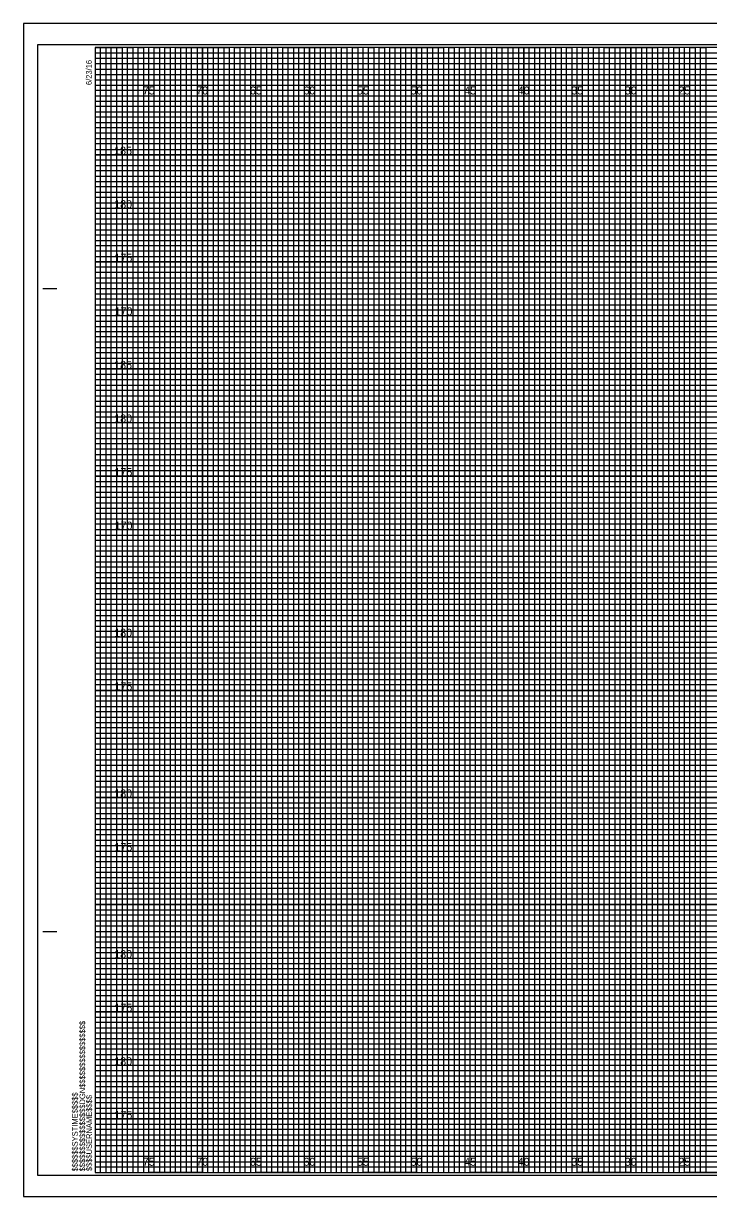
# Model space of a CAD drawing. Extents: x -7 to 162, y -2 to 767.
# Drawn here: x -6.7 to 57.2, y -2.2 to 107.2 of the extents above; entities that cross this region are included whole.
import ezdxf

# ---------------------------------------------------------------- set-up
doc = ezdxf.new("R2010")
doc.units = 0
for name, color, linetype in [('Exist Cross Section Cell', 7, 'Continuous'), ('Prop CMT Pvmt Course 1', 7, 'Continuous'), ('Prop CMT Pvmt Course 1 Wedge', 7, 'Continuous'), ('Prop CMT Pvmt Course 2', 7, 'Continuous'), ('Prop CMT Pvmt Course 3', 7, 'Continuous'), ('Prop CMT Pvmt Surface Shoulder', 7, 'Continuous'), ('Prop CMT Shld Paved Course 2', 7, 'Continuous'), ('Prop CMT Shld Paved Course 3', 7, 'Continuous'), ('Prop CMT Slope Grass', 7, 'Continuous'), ('Prop CMT Subgrade Earthwork', 7, 'Continuous'), ('Scratch_Level_0', 7, 'Continuous')]:
    doc.layers.add(name, color=color, linetype=linetype)

msp = doc.modelspace()

# ---------------------------------------------------------------- linework, layer by layer
at = {"layer": 'Prop CMT Pvmt Course 1'}
for p, q in [((0, 104.5), (130, 104.5)), ((130, 103.99), (0, 103.99)), ((0, 103.99), (0, 103.5)), ((0, 103.5), (130, 103.5)), ((130, 102.95), (0, 102.95)), ((0, 102.95), (0, 102)), ((0, 102), (160, 102))]:
    msp.add_line(p, q, dxfattribs=at)
for points in [[(0, 101.5), (135, 101.5), (160, 101.5), (160, 101), (0, 101)], [(0, 100.5), (160, 100.5), (160, 99.5), (0, 99.5)], [(0, 99), (160, 99), (160, 98.5), (0, 98.49)], [(0, 98), (160, 98), (160, 97), (0, 97)], [(0, 96.5), (160, 96.5), (160, 96), (0, 96)], [(0, 95.5), (160, 95.5), (160, 94.5), (0, 94.5)], [(0, 94), (160, 94), (160, 93.5), (0, 93.5)], [(0, 93), (160, 93), (160, 92), (0, 92)], [(0, 91.5), (160, 91.5), (160, 91), (0, 91)], [(0, 90.5), (160, 90.5), (160, 89.5), (0, 89.5)], [(0, 89), (160, 89), (160, 88.5), (0, 88.5)], [(0, 88), (160, 88), (160, 86.98), (160, 86.5), (160, 86), (0, 86)], [(0, 87), (160, 87), (160, 86.5), (0, 86.5)], [(0, 85.5), (160, 85.5), (160, 84.5), (0, 84.52)], [(0, 84.52), (160, 84.5), (160, 84), (0, 84)], [(0, 83.5), (160, 83.5), (160, 83), (0, 83)], [(0, 82), (160, 82), (160, 81.5), (0, 81.5)], [(0, 81), (160, 81), (160, 80.5), (0, 80.5)], [(-0.04, 79.45), (160, 79.45), (160, 78.94), (-0.04, 78.94)], [(0, 78.5), (160, 78.5), (160, 78), (0, 78)], [(0, 77), (160, 77), (160, 76.5), (0, 76.5)], [(0, 76), (160, 76), (160, 75.5), (0, 75.5)], [(0, 74.5), (160, 74.5), (160, 74), (0, 74)], [(0, 73.5), (160, 73.5), (160, 73), (0, 73)], [(0, 72), (160, 72), (160, 71.5), (0, 71.5)], [(0, 71), (160, 71), (160, 70.5), (0, 70.5)], [(0, 69.5), (160, 69.5), (160, 68.99), (0, 69)], [(0, 68.5), (160, 68.5), (160, 68), (0, 68)], [(0, 67), (160, 67), (160, 66.5), (0, 66.5)], [(0, 66), (160, 66), (160, 65.5), (0, 65.5)], [(0, 64.5), (160, 64.5), (160, 64), (0, 64)], [(0, 63.5), (160, 63.5), (160, 63), (0, 63)], [(0, 62), (160, 62), (160, 61.5), (0, 61.5)], [(0, 61), (160, 61), (160, 60.5), (0, 60.5)], [(0, 59.5), (160, 59.5), (160, 59), (0, 59)], [(0, 58.5), (160.03, 58.45), (160, 58), (0, 58)], [(0, 57), (160, 57), (160, 56.5), (0, 56.5)], [(0, 56), (160, 56), (160, 55.5), (0, 55.5)], [(0, 54.5), (160, 54.5), (160, 54), (0, 54)], [(0, 53.5), (160, 53.5), (160, 53), (0, 53)], [(0, 52), (160, 52), (160, 51.5), (0, 51.5)], [(0, 51), (160, 51), (160, 50.5), (0, 50.5)], [(0, 49.5), (160, 49.5), (160, 49), (0, 49)], [(0, 48.5), (160, 48.5), (160, 48), (0, 48)], [(0, 47), (160, 47), (160, 46.5), (0, 46.5)], [(0, 46), (160, 46), (160, 45.5), (0, 45.5)], [(0, 44.5), (160, 44.5), (160, 44), (0, 44)], [(0, 43.5), (160, 43.5), (160, 43), (0, 43)], [(0, 42), (160, 42), (160, 41.5), (0, 41.5)], [(0, 41), (160, 41), (160, 40.5), (0, 40.5)], [(0, 39.5), (160, 39.5), (160, 38.99), (0, 39)], [(0, 38.5), (160, 38.5), (160, 38), (0, 38)], [(0, 37), (160, 37), (160, 36.5), (0, 36.5)], [(0, 36), (160, 36), (160, 35.5), (0, 35.5)], [(0, 34.5), (160, 34.5), (160, 34), (0, 34)], [(0, 33.5), (160, 33.5), (160, 33), (0, 33)], [(0, 32), (160, 32), (160, 31.5), (0, 31.5)], [(0, 31), (160, 31), (160, 30.5), (0, 30.5)], [(0, 29.5), (160, 29.5), (160, 29), (0, 29)], [(0, 28.5), (160.03, 28.46), (160, 28), (0, 28)], [(0, 27), (160, 27), (160, 26.5), (0, 26.5)], [(0, 26), (160, 26), (160, 25.5), (0, 25.5)], [(0, 24.5), (160, 24.5), (160, 24), (0, 24)], [(0, 23.5), (160, 23.5), (160, 23), (0, 23)], [(0, 22), (160, 22), (160, 21.5), (0, 21.5)], [(0, 21), (160, 21), (160, 20.5), (0, 20.5)], [(0, 19.5), (160, 19.5), (160, 19), (0, 19)], [(0, 18.5), (160, 18.5), (160, 18), (0, 18)], [(0, 17), (160, 17), (160, 16.5), (0, 16.5)], [(0, 16), (160, 16), (160, 15.5), (0, 15.5)], [(0, 14.5), (160, 14.5), (160, 14), (0, 14)], [(0, 13.5), (160, 13.5), (160, 13), (0, 13)], [(0, 12), (160, 12), (160, 11.5), (0, 11.5)], [(0, 11), (160, 11), (160, 10.5), (0, 10.5)], [(0, 9.5), (160, 9.5), (160, 9), (0, 9)], [(0, 8.5), (160, 8.5), (160, 8), (0, 8)], [(0, 7), (160, 7), (160, 6.5), (0, 6.5)], [(0, 6), (160, 6), (160, 5.5), (0, 5.5)], [(0, 4.5), (160, 4.5), (160, 4), (0, 4)], [(0, 3.5), (160, 3.5), (160, 3), (0, 3)], [(0, 2), (160, 2), (160, 1.5), (0, 1.5)], [(0, 1), (160, 1), (160, 0.5), (0, 0.5)]]:
    msp.add_lwpolyline(points, dxfattribs=at)
at = {"layer": 'Prop CMT Pvmt Course 2'}
for p, q in [((5, 0), (5, 105)), ((10, 0), (10, 105)), ((15, 0), (15, 105)), ((20, 0), (20, 105)), ((25, 0), (25, 105)), ((30, 0), (30, 105)), ((35, 0), (35, 105)), ((40, 0), (40, 105)), ((45, 0), (45, 105)), ((50, 0), (50, 105)), ((55, 0), (55, 105)), ((0, 100), (160, 100)), ((0, 95), (160, 95)), ((0, 90), (160, 90)), ((0, 85), (160, 85)), ((0, 80), (160, 80)), ((0, 75), (160, 75)), ((0, 70), (160, 70)), ((0, 65), (160, 65)), ((0, 60), (160, 60)), ((0, 55), (160, 55)), ((0, 50), (160, 50)), ((0, 45), (160, 45)), ((0, 40), (160, 40)), ((0, 35), (160, 35)), ((0, 30), (160, 30)), ((0, 25), (160, 25)), ((0, 20), (160, 20)), ((0, 15), (160, 15)), ((0, 10), (160, 10)), ((0, 5), (160, 5))]:
    msp.add_line(p, q, dxfattribs=at)
at = {"layer": 'Prop CMT Pvmt Course 3'}
for p, q in [((161.65, 107.25), (-6.7, 107.25)), ((-6.7, 107.25), (-6.7, -2.25)), ((-6.7, -2.25), (161.65, -2.25))]:
    msp.add_line(p, q, dxfattribs=at)
at = {"layer": 'Prop CMT Pvmt Surface Shoulder'}
for points in [[(0, 105), (2.5, 105), (2.5, 0), (7.5, 0), (7.5, 105), (12.5, 105), (12.5, 0), (17.5, 0), (17.5, 105), (22.5, 105), (22.5, 0), (27.5, 0), (27.5, 105), (32.5, 105), (32.5, 0), (37.5, 0), (37.5, 105), (42.5, 105), (42.5, 0), (47.5, 0), (47.5, 105), (52.5, 105), (52.5, 0), (57.5, 0)], [(0, 102.5), (137.5, 102.5)], [(0, 92.5), (160, 92.5), (160, 97.5), (0, 97.5)], [(0, 82.5), (160, 82.5), (160, 87.5), (0, 87.5)], [(0, 72.5), (160, 72.5), (160, 77.5), (0, 77.5)], [(0, 62.5), (160, 62.5), (160, 67.5), (0, 67.5)], [(0, 52.5), (160, 52.5), (160, 57.5), (0, 57.5)], [(0, 42.5), (160, 42.5), (160, 47.5), (0, 47.5)], [(0, 32.5), (160, 32.5), (160, 37.5), (0, 37.5)], [(0, 22.5), (160, 22.5), (160, 27.5), (0, 27.5)], [(0, 12.5), (160, 12.5), (160, 17.5), (0, 17.5)], [(0, 2.5), (160, 2.5), (160, 7.5), (0, 7.5)]]:
    msp.add_lwpolyline(points, dxfattribs=at)
at = {"layer": 'Prop CMT Shld Paved Course 2'}
msp.add_lwpolyline([(-6.7, -2.25), (161.65, -2.25), (161.65, 107.25), (-6.7, 107.25)], close=True, dxfattribs=at)
at = {"layer": 'Prop CMT Shld Paved Course 3'}
msp.add_lwpolyline([(-5.4, -0.25), (161.2, -0.25), (161.2, 105.25), (-5.4, 105.25)], close=True, dxfattribs=at)
at = {"layer": 'Prop CMT Slope Grass'}
for points in [[(0, 0), (0.5, 0), (0.5, 105), (1, 105), (1, 0)], [(1, 0), (1.5, 0), (1.5, 105), (2, 105), (2, 0)], [(2.5, 0), (3, 0), (3, 105), (3.5, 105), (3.5, 0)], [(3.5, 0), (4, 0), (4, 105), (4.5, 105), (4.5, 0)], [(5, 0), (5.5, 0), (5.5, 105), (6, 105), (6, 0)], [(6, 0), (6.5, 0), (6.5, 105), (7, 105), (7, 0)], [(7.5, 0), (8, 0), (8, 105), (8.5, 105), (8.5, 0)], [(8.5, 0), (9, 0), (9, 105), (9.5, 105), (9.5, 0)], [(10, 0), (10.5, 0), (10.5, 105), (11, 105), (11, 0)], [(11, 0), (11.5, 0), (11.5, 105), (12, 105), (12, 0)], [(12.5, 0), (13, 0), (13, 105), (13.5, 105), (13.5, 0)], [(13.5, 0), (14, 0), (14, 105), (14.5, 105), (14.5, 0)], [(15, 0), (15.5, 0), (15.5, 105), (16, 105), (16, 0)], [(16, 0), (16.5, 0), (16.5, 105), (17, 105), (17, 0)], [(17.5, 0), (18, 0), (18, 105), (18.5, 105), (18.5, 0)], [(18.5, 0), (19, 0), (19, 105), (19.5, 105), (19.5, 0)], [(20, 0), (20.5, 0), (20.5, 105), (21, 105), (21, 0)], [(21, 0), (21.5, 0), (21.5, 105), (22, 105), (22, 0)], [(22.5, 0), (23, 0), (23, 105), (23.5, 105), (23.5, 0)], [(23.5, 0), (24, 0), (24, 105), (24.5, 105), (24.5, 0)], [(25, 0), (25.5, 0), (25.5, 105), (26, 105), (26, 0)], [(26, 0), (26.5, 0), (26.5, 105), (27, 105), (27, 0)], [(27.5, 0), (28, 0), (28, 105), (28.5, 105), (28.5, 0)], [(28.5, 0), (29, 0), (29, 105), (29.5, 105), (29.5, 0)], [(30, 0), (30.5, 0), (30.5, 105), (31, 105), (31, 0)], [(31, 0), (31.5, 0), (31.5, 105), (32, 105), (32, 0)], [(32.5, 0), (33, 0), (33, 105), (33.5, 105), (33.5, 0)], [(33.5, 0), (34, 0), (34, 105), (34.5, 105), (34.5, 0)], [(35, 0), (35.5, 0), (35.5, 105), (36, 105), (36, 0)], [(36, 0), (36.5, 0), (36.5, 105), (37, 105), (37, 0)], [(37.5, 0), (38, 0), (38, 105), (38.5, 105), (38.5, 0)], [(38.5, 0), (39, 0), (39, 105), (39.5, 105), (39.5, 0)], [(40, 0), (40.5, 0), (40.5, 105), (41, 105), (41, 0)], [(41, 0), (41.5, 0), (41.5, 105), (42, 105), (42, 0)], [(42.5, 0), (43, 0), (43, 105), (43.5, 105), (43.5, 0)], [(43.5, 0), (44, 0), (44, 105), (44.5, 105), (44.5, 0)], [(45, 0), (45.5, 0), (45.5, 105), (46, 105), (46, 0)], [(46, 0), (46.5, 0), (46.5, 105), (47, 105), (47, 0)], [(47.5, 0), (48, 0), (48, 105), (48.5, 105), (48.5, 0)], [(48.5, 0), (49, 0), (49, 105), (49.5, 105), (49.5, 0)], [(50, 0), (50.5, 0), (50.5, 105), (51, 105), (51, 0)], [(51, 0), (51.5, 0), (51.5, 105), (52, 105), (52, 0)], [(52.5, 0), (53, 0), (53, 105), (53.5, 105), (53.5, 0)], [(53.5, 0), (54, 0), (54, 105), (54.5, 105), (54.5, 0)], [(55, 0), (55.5, 0), (55.5, 105), (56, 105), (56, 0)], [(56, 0), (56.5, 0), (56.5, 105), (57, 105), (57, 0)]]:
    msp.add_lwpolyline(points, dxfattribs=at)
at = {"layer": 'Prop CMT Subgrade Earthwork'}
for p, q in [((-4.9, 82.5), (-3.65, 82.5)), ((-4.85, 82.5), (-3.6, 82.5)), ((-4.9, 22.5), (-3.65, 22.5)), ((-4.85, 22.5), (-3.6, 22.5)), ((0, 0), (0, 0)), ((0, 0), (0, 0)), ((0, 0), (0, 0)), ((0, 0), (0, 0)), ((0, 0), (0, 0)), ((0, 0), (0, 0)), ((0, 0), (0, 0))]:
    msp.add_line(p, q, dxfattribs=at)
msp.add_lwpolyline([(160, 105), (0, 105), (0, 0), (160, 0)], close=True, dxfattribs=at)
at = {"layer": 'Scratch_Level_0'}
for p, q in [((5, 105), (0, 105)), ((5, 0), (5, 105)), ((15, 105), (10, 105)), ((10, 105), (10, 0)), ((15, 0), (15, 105)), ((25, 105), (20, 105)), ((20, 105), (20, 0)), ((25, 0), (25, 105)), ((35, 105), (30, 105)), ((30, 105), (30, 0)), ((35, 0), (35, 105)), ((45, 105), (40, 105)), ((40, 105), (40, 0)), ((45, 0), (45, 105)), ((55, 105), (50, 105)), ((50, 105), (50, 0)), ((55, 0), (55, 105)), ((10, 0), (5, 0)), ((20, 0), (15, 0)), ((30, 0), (25, 0)), ((40, 0), (35, 0)), ((50, 0), (45, 0)), ((60, 0), (55, 0))]:
    msp.add_line(p, q, dxfattribs=at)
for points in [[(0, 100), (160, 100), (160, 95), (0, 95)], [(0, 90), (160, 90), (160, 85), (0, 85)], [(0, 80), (160, 80), (160, 75), (0, 75)], [(0, 70), (160, 70), (160, 65), (0, 65)], [(0, 60), (160, 60), (160, 55), (0, 55)], [(0, 50), (160, 50), (160, 45), (0, 45)], [(0, 40), (160, 40), (160, 35), (0, 35)], [(0, 30), (160, 30), (160, 25), (0, 25)], [(0, 20), (160, 20), (160, 15), (0, 15)], [(0, 10), (160, 10), (160, 5), (0, 5)]]:
    msp.add_lwpolyline(points, dxfattribs=at)

# ---------------------------------------------------------------- texts
at = {"layer": 'Exist Cross Section Cell'}
for s, p in [('75', (4.44, 100.62)), ('70', (9.43, 100.62)), ('65', (14.44, 100.62)), ('60', (19.43, 100.62)), ('55', (24.44, 100.62)), ('50', (29.43, 100.62)), ('45', (34.44, 100.62)), ('40', (39.43, 100.62)), ('35', (44.44, 100.62)), ('30', (49.43, 100.62)), ('25', (54.44, 100.62)), ('75', (4.44, 0.62)), ('70', (9.43, 0.62)), ('65', (14.44, 0.62)), ('60', (19.43, 0.62)), ('55', (24.44, 0.62)), ('50', (29.43, 0.62)), ('45', (34.44, 0.62)), ('40', (39.43, 0.62)), ('35', (44.44, 0.62)), ('30', (49.43, 0.62)), ('25', (54.44, 0.62))]:
    msp.add_text(s, height=0.75, dxfattribs=at).set_placement(p)
at = {"layer": 'Prop CMT Pvmt Course 1 Wedge'}
for s, p in [('185', (1.76, 95)), ('180', (1.77, 90)), ('175', (1.79, 85)), ('170', (1.8, 80)), ('185', (1.76, 75)), ('180', (1.77, 70)), ('175', (1.79, 65)), ('170', (1.8, 60)), ('180', (1.77, 50)), ('175', (1.79, 45)), ('180', (1.77, 35)), ('175', (1.79, 30)), ('180', (1.77, 20)), ('175', (1.79, 15)), ('180', (1.77, 10)), ('175', (1.79, 5))]:
    msp.add_text(s, height=0.75, dxfattribs=at).set_placement(p)
at = {"layer": 'Prop CMT Subgrade Earthwork'}
for s, p in [('6/23/16', (-0.33, 101.5)), ('$$$$$$$$$$$$$$$$DGN$$$$$$$$$$$$$$$$', (-0.94, 0.09)), ('$$$$$$SYSTIME$$$$$', (-1.63, 0.09)), ('$$$$USERNAME$$$$', (-0.31, 0.12))]:
    msp.add_text(s, height=0.525, rotation=90, dxfattribs=at).set_placement(p)

doc.saveas('drawing.dxf')
